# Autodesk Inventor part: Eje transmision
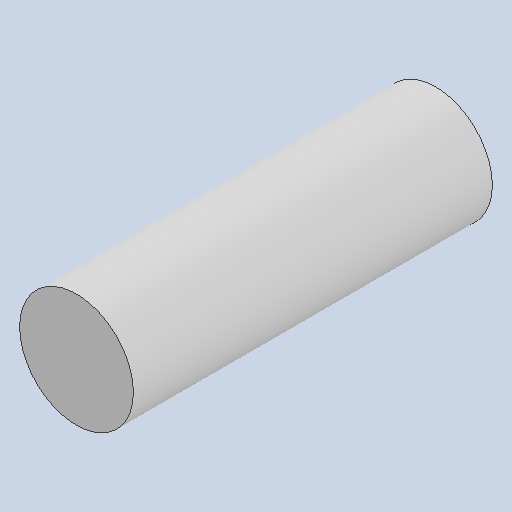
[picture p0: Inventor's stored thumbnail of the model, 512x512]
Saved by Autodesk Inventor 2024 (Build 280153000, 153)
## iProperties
Created: 2024-05
Part Number: Eje transmision
Material: Generic
Document SubType Name: Modeling
Designer: dylan
Density: 1 g/cm^3
Appearance: Default
Author: dylan
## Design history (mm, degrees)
sketch "Sketch1"
  geometry: C1 r 4.75 at (25, 0); A1 r 5 centre (25, 0) between (30, -0.066) and (20, 0.066) reference; 1 further point
  constraints: 1 centre point, 1 coincident
  dimensions: "d0" = 9.5 diameter of C1
extrude "Extrusion1" new body sketch "Sketch1" distance "d1" = 30; taper "d2" = 0 deg
body "Solid1"
node "Reference1"
